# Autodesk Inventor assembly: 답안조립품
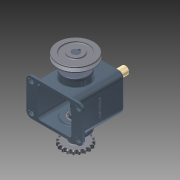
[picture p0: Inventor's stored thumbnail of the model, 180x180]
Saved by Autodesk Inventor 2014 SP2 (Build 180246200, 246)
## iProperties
Created: 2015-01
Part Number: 답안조립품
Document SubType Name: Assembly
Designer: 201-09
Author: 201-09
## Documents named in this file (15)
- C:\Users\201-09\Desktop\350105V1011\답안조립품.iam
- C:\Users\201-09\Desktop\350105V1011\1.본체.ipt
- C:\Users\201-09\Desktop\350105V1011\2.편심축.ipt
- C:\Users\201-09\Desktop\350105V1011\3.V-벨트풀리.ipt
- C:\Users\201-09\Desktop\350105V1011\4.체인 스프로킷.ipt
- C:\Users\201-09\Desktop\350105V1011\5.커버.ipt
- C:\Users\201-09\Desktop\350105V1011\6.슬라이드.ipt
- C:\Users\201-09\Desktop\350105V1011\8.베어링 6205.ipt
- C:\Users\201-09\Desktop\350105V1011\9.오일실.ipt
- C:\Users\201-09\Desktop\350105V1011\10.부시.ipt
- C:\Users\201-09\Desktop\350105V1011\11.키 8x8.ipt
- C:\Users\201-09\Desktop\350105V1011\12.멈춤링.ipt
- C:\Users\201-09\Desktop\350105V1011\13.M4x0.5.ipt
- C:\Users\201-09\Desktop\350105V1011\14.멈춤나사 M5x0.5.ipt
- C:\Users\201-09\Desktop\350105V1011\7.스프링-[가변].ipt
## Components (13 placed, 7 different names)
1. 1.본체:1 — 플러쉬:2
2. 2.편심축:1 — 각도:1, 각도:2
3. 3.V-벨트풀리:1 — 각도:3
4. 5-체인 스프로킷:1 — 각도:4
5. 5.커버:1
6. 5.커버:2
7. M4x0.5:1
8. M4x0.5:2
9. M4x0.5:3
10. M4x0.5:4
11. M4x0.5:5
12. M4x0.5:6
13. 7.스프링-[가변]:1 — 플러쉬:1, 플러쉬:2
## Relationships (6: Angle 4, Flush 2)
- 각도:1 [Angle]: 2.편심축:1
- 각도:2 [Angle]: 2.편심축:1
- 각도:3 [Angle]: 3.V-벨트풀리:1
- 각도:4 [Angle]: 5-체인 스프로킷:1
- 플러쉬:1 [Flush]: 7.스프링-[가변]:1
- 플러쉬:2 [Flush]: 1.본체:1 ↔ 7.스프링-[가변]:1
